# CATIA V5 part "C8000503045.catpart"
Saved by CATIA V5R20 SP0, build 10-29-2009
Part number: C8000503045
Source: Unknown
Property "A": "45"
Property "ARTICLENO": "C8000503045"
Property "B": "22"
Property "BOMINFO": "C8000503045"
Property "C": "65"
Property "CA": "C8000503045"
Property "D1": "75"
Property "DES": "ROTATING EYEBOLT WITH RING Ton 5,3 M30x45"
Property "E": "80"
Property "H": "165"
Property "L": "45"
Property "LINA": "C8000503045"
Property "NB": "C8000503045"
Property "NBSYN": "$CODE."
Property "NN": "C800"
Property "NT": "Rotating eyebolt with ring"
Property "SIZE": "M30"
Property "SUPPLIER": "CF"
Property "SW": "65"
Property "WEIGHT": "2230"
Property "WLL": "5.30"
Bounding box of the stored display mesh (mm): x -44.333 to 44.5, y -45 to 186.644, z -37.5 to 37.5
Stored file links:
  C:\Users\Utente\Desktop\3D files 800\C8000503045.catpart
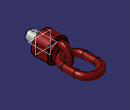
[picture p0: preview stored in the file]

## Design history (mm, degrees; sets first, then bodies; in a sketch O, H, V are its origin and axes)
Body1 "Geometry.1" (main body)
  Solid1 "C8000503045.catpart": solid without history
